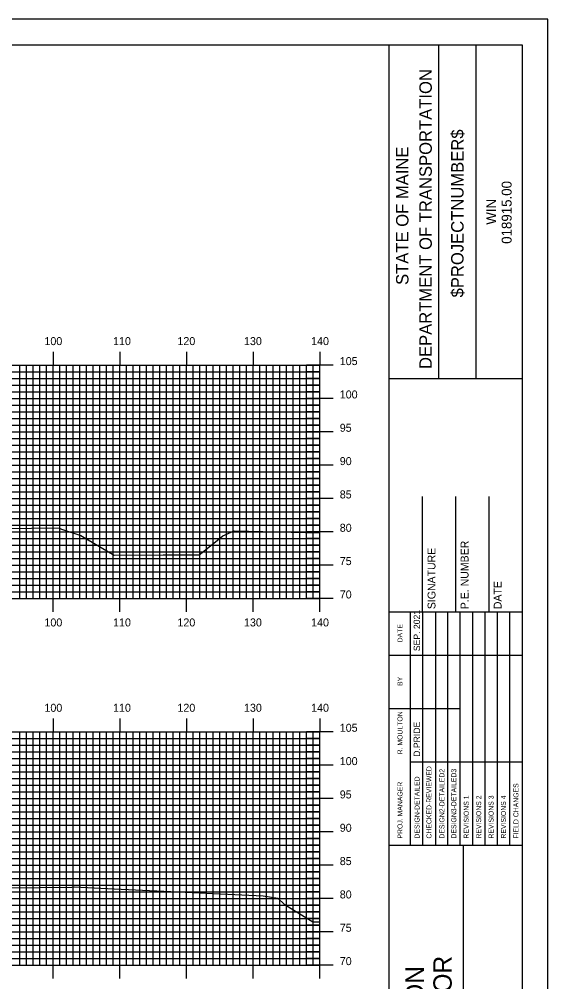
# Model space of a CAD drawing. Extents: x 1756282 to 1756625, y 442591 to 442811.
# Drawn here: x 1756542.5 to 1756621.8, y 442666.2 to 442810.5 of the extents above; entities that cross this region are included whole.
import ezdxf

# ---------------------------------------------------------------- set-up
doc = ezdxf.new("R2010")
doc.units = 0
for name, color, linetype in [('BORDER', 7, 'Continuous'), ('H_V ANNOTATION', 7, 'Continuous'), ('MAJOR', 7, 'Continuous'), ('MINOR', 7, 'Continuous'), ('PLOT BOUNDARY', 7, 'Continuous'), ('S_Roadway_Centerline', 7, 'Continuous')]:
    doc.layers.add(name, color=color, linetype=linetype)

msp = doc.modelspace()

# ---------------------------------------------------------------- linework, layer by layer
at = {"layer": 'BORDER'}
for p, q in [((1756597.97, 442596.67), (1756597.97, 442806.67)), ((1756605.43, 442756.66), (1756605.43, 442806.66)), ((1756611.02, 442756.66), (1756611.02, 442806.66)), ((1756597.97, 442756.65), (1756617.97, 442756.65)), ((1756602.97, 442721.67), (1756602.97, 442738.97)), ((1756607.97, 442721.67), (1756607.97, 442738.97)), ((1756612.97, 442721.67), (1756612.97, 442738.97)), ((1756597.97, 442721.67), (1756617.97, 442721.67)), ((1756597.97, 442686.67), (1756617.97, 442686.67)), ((1756609.15, 442616.67), (1756609.15, 442686.67))]:
    msp.add_line(p, q, dxfattribs=at)
msp.add_lwpolyline([(1756297.97, 442596.67), (1756617.97, 442596.67), (1756617.97, 442806.67), (1756297.97, 442806.67)], close=True, dxfattribs=at)
for points in [[(1756601.2, 442715.17), (1756601.2, 442721.67)], [(1756603.06, 442686.68), (1756603.06, 442721.67)], [(1756604.93, 442721.67), (1756604.93, 442686.68)], [(1756606.79, 442686.68), (1756606.79, 442721.67)], [(1756608.65, 442686.68), (1756608.65, 442721.67)], [(1756610.52, 442686.68), (1756610.52, 442721.67)], [(1756612.38, 442686.68), (1756612.38, 442721.67)], [(1756614.24, 442686.68), (1756614.24, 442721.67)], [(1756616.11, 442686.68), (1756616.11, 442721.67)], [(1756601.2, 442686.68), (1756601.2, 442720.26)], [(1756597.97, 442715.17), (1756617.97, 442715.17)], [(1756597.97, 442707.17), (1756601.2, 442707.17)], [(1756601.2, 442707.17), (1756608.65, 442707.17)], [(1756601.2, 442699.17), (1756617.97, 442699.17)]]:
    msp.add_lwpolyline(points, dxfattribs=at)
at = {"layer": 'MAJOR'}
for p, q in [((1756547.57, 442760.67), (1756547.57, 442758.67)), ((1756557.57, 442760.67), (1756557.57, 442758.67)), ((1756567.57, 442760.67), (1756567.57, 442758.67)), ((1756577.57, 442760.67), (1756577.57, 442758.67)), ((1756587.57, 442760.67), (1756587.57, 442758.67)), ((1756307.57, 442758.67), (1756587.57, 442758.67)), ((1756307.57, 442758.67), (1756587.57, 442758.67)), ((1756547.57, 442723.67), (1756547.57, 442758.67)), ((1756557.57, 442723.67), (1756557.57, 442758.67)), ((1756567.57, 442723.67), (1756567.57, 442758.67)), ((1756577.57, 442723.67), (1756577.57, 442758.67)), ((1756589.57, 442758.67), (1756585.57, 442758.67)), ((1756587.57, 442723.67), (1756587.57, 442758.67)), ((1756587.57, 442723.67), (1756587.57, 442758.67)), ((1756307.57, 442753.67), (1756587.57, 442753.67)), ((1756589.57, 442753.67), (1756585.57, 442753.67)), ((1756307.57, 442748.67), (1756587.57, 442748.67)), ((1756589.57, 442748.67), (1756585.57, 442748.67)), ((1756307.57, 442743.67), (1756587.57, 442743.67)), ((1756589.57, 442743.67), (1756585.57, 442743.67)), ((1756307.57, 442738.67), (1756587.57, 442738.67)), ((1756589.57, 442738.67), (1756585.57, 442738.67)), ((1756307.57, 442733.67), (1756587.57, 442733.67)), ((1756589.57, 442733.67), (1756585.57, 442733.67)), ((1756307.57, 442728.67), (1756587.57, 442728.67)), ((1756589.57, 442728.67), (1756585.57, 442728.67)), ((1756307.57, 442723.67), (1756587.57, 442723.67)), ((1756307.57, 442723.67), (1756587.57, 442723.67)), ((1756547.57, 442721.66), (1756547.57, 442723.67)), ((1756557.57, 442721.66), (1756557.57, 442723.67)), ((1756567.57, 442721.66), (1756567.57, 442723.67)), ((1756577.57, 442721.66), (1756577.57, 442723.67)), ((1756589.57, 442723.67), (1756585.57, 442723.67)), ((1756587.57, 442721.66), (1756587.57, 442723.67)), ((1756547.57, 442705.67), (1756547.57, 442703.67)), ((1756557.57, 442705.67), (1756557.57, 442703.67)), ((1756567.57, 442705.67), (1756567.57, 442703.67)), ((1756577.57, 442705.67), (1756577.57, 442703.67)), ((1756587.57, 442705.67), (1756587.57, 442703.67)), ((1756307.57, 442703.67), (1756587.57, 442703.67)), ((1756307.57, 442703.67), (1756587.57, 442703.67)), ((1756547.57, 442668.67), (1756547.57, 442703.67)), ((1756557.57, 442668.67), (1756557.57, 442703.67)), ((1756567.57, 442668.67), (1756567.57, 442703.67)), ((1756577.57, 442668.67), (1756577.57, 442703.67)), ((1756589.57, 442703.67), (1756585.57, 442703.67)), ((1756587.57, 442668.67), (1756587.57, 442703.67)), ((1756587.57, 442668.67), (1756587.57, 442703.67)), ((1756307.57, 442698.67), (1756587.57, 442698.67)), ((1756589.57, 442698.67), (1756585.57, 442698.67)), ((1756307.57, 442693.67), (1756587.57, 442693.67)), ((1756589.57, 442693.67), (1756585.57, 442693.67)), ((1756307.57, 442688.67), (1756587.57, 442688.67)), ((1756589.57, 442688.67), (1756585.57, 442688.67)), ((1756307.57, 442683.67), (1756587.57, 442683.67)), ((1756589.57, 442683.67), (1756585.57, 442683.67)), ((1756307.57, 442678.67), (1756587.57, 442678.67)), ((1756589.57, 442678.67), (1756585.57, 442678.67)), ((1756307.57, 442673.67), (1756587.57, 442673.67)), ((1756589.57, 442673.67), (1756585.57, 442673.67)), ((1756307.57, 442668.67), (1756587.57, 442668.67)), ((1756307.57, 442668.67), (1756587.57, 442668.67)), ((1756547.57, 442666.66), (1756547.57, 442668.67)), ((1756557.57, 442666.66), (1756557.57, 442668.67)), ((1756567.57, 442666.66), (1756567.57, 442668.67)), ((1756577.57, 442666.66), (1756577.57, 442668.67)), ((1756589.57, 442668.67), (1756585.57, 442668.67)), ((1756587.57, 442666.66), (1756587.57, 442668.67))]:
    msp.add_line(p, q, dxfattribs=at)
at = {"layer": 'MINOR'}
for p, q in [((1756542.57, 442723.67), (1756542.57, 442758.67)), ((1756543.57, 442723.67), (1756543.57, 442758.67)), ((1756544.57, 442723.67), (1756544.57, 442758.67)), ((1756545.57, 442723.67), (1756545.57, 442758.67)), ((1756546.57, 442723.67), (1756546.57, 442758.67)), ((1756548.57, 442723.67), (1756548.57, 442758.67)), ((1756549.57, 442723.67), (1756549.57, 442758.67)), ((1756550.57, 442723.67), (1756550.57, 442758.67)), ((1756551.57, 442723.67), (1756551.57, 442758.67)), ((1756552.57, 442723.67), (1756552.57, 442758.67)), ((1756553.57, 442723.67), (1756553.57, 442758.67)), ((1756554.57, 442723.67), (1756554.57, 442758.67)), ((1756555.57, 442723.67), (1756555.57, 442758.67)), ((1756556.57, 442723.67), (1756556.57, 442758.67)), ((1756558.57, 442723.67), (1756558.57, 442758.67)), ((1756559.57, 442723.67), (1756559.57, 442758.67)), ((1756560.57, 442723.67), (1756560.57, 442758.67)), ((1756561.57, 442723.67), (1756561.57, 442758.67)), ((1756562.57, 442723.67), (1756562.57, 442758.67)), ((1756563.57, 442723.67), (1756563.57, 442758.67)), ((1756564.57, 442723.67), (1756564.57, 442758.67)), ((1756565.57, 442723.67), (1756565.57, 442758.67)), ((1756566.57, 442723.67), (1756566.57, 442758.67)), ((1756568.57, 442723.67), (1756568.57, 442758.67)), ((1756569.57, 442723.67), (1756569.57, 442758.67)), ((1756570.57, 442723.67), (1756570.57, 442758.67)), ((1756571.57, 442723.67), (1756571.57, 442758.67)), ((1756572.57, 442723.67), (1756572.57, 442758.67)), ((1756573.57, 442723.67), (1756573.57, 442758.67)), ((1756574.57, 442723.67), (1756574.57, 442758.67)), ((1756575.57, 442723.67), (1756575.57, 442758.67)), ((1756576.57, 442723.67), (1756576.57, 442758.67)), ((1756578.57, 442723.67), (1756578.57, 442758.67)), ((1756579.57, 442723.67), (1756579.57, 442758.67)), ((1756580.57, 442723.67), (1756580.57, 442758.67)), ((1756581.57, 442723.67), (1756581.57, 442758.67)), ((1756582.57, 442723.67), (1756582.57, 442758.67)), ((1756583.57, 442723.67), (1756583.57, 442758.67)), ((1756584.57, 442723.67), (1756584.57, 442758.67)), ((1756585.57, 442723.67), (1756585.57, 442758.67)), ((1756586.57, 442723.67), (1756586.57, 442758.67)), ((1756307.57, 442757.67), (1756587.57, 442757.67)), ((1756587.57, 442757.67), (1756585.57, 442757.67)), ((1756307.57, 442756.67), (1756587.57, 442756.67)), ((1756307.57, 442755.67), (1756587.57, 442755.67)), ((1756587.57, 442756.67), (1756585.57, 442756.67)), ((1756587.57, 442755.67), (1756585.57, 442755.67)), ((1756307.57, 442754.67), (1756587.57, 442754.67)), ((1756587.57, 442754.67), (1756585.57, 442754.67)), ((1756307.57, 442752.67), (1756587.57, 442752.67)), ((1756307.57, 442751.67), (1756587.57, 442751.67)), ((1756587.57, 442752.67), (1756585.57, 442752.67)), ((1756587.57, 442751.67), (1756585.57, 442751.67)), ((1756307.57, 442750.67), (1756587.57, 442750.67)), ((1756587.57, 442750.67), (1756585.57, 442750.67)), ((1756307.57, 442749.67), (1756587.57, 442749.67)), ((1756587.57, 442749.67), (1756585.57, 442749.67)), ((1756307.57, 442747.67), (1756587.57, 442747.67)), ((1756587.57, 442747.67), (1756585.57, 442747.67)), ((1756307.57, 442746.67), (1756587.57, 442746.67)), ((1756307.57, 442745.67), (1756587.57, 442745.67)), ((1756587.57, 442746.67), (1756585.57, 442746.67)), ((1756587.57, 442745.67), (1756585.57, 442745.67)), ((1756307.57, 442744.67), (1756587.57, 442744.67)), ((1756587.57, 442744.67), (1756585.57, 442744.67)), ((1756307.57, 442742.67), (1756587.57, 442742.67)), ((1756587.57, 442742.67), (1756585.57, 442742.67)), ((1756307.57, 442741.67), (1756587.57, 442741.67)), ((1756587.57, 442741.67), (1756585.57, 442741.67)), ((1756307.57, 442740.67), (1756587.57, 442740.67)), ((1756587.57, 442740.67), (1756585.57, 442740.67)), ((1756307.57, 442739.67), (1756587.57, 442739.67)), ((1756587.57, 442739.67), (1756585.57, 442739.67)), ((1756307.57, 442737.67), (1756587.57, 442737.67)), ((1756587.57, 442737.67), (1756585.57, 442737.67)), ((1756307.57, 442736.67), (1756587.57, 442736.67)), ((1756307.57, 442735.67), (1756587.57, 442735.67)), ((1756587.57, 442736.67), (1756585.57, 442736.67)), ((1756587.57, 442735.67), (1756585.57, 442735.67)), ((1756307.57, 442734.67), (1756587.57, 442734.67)), ((1756587.57, 442734.67), (1756585.57, 442734.67)), ((1756307.57, 442732.67), (1756587.57, 442732.67)), ((1756587.57, 442732.67), (1756585.57, 442732.67)), ((1756307.57, 442731.67), (1756587.57, 442731.67)), ((1756587.57, 442731.67), (1756585.57, 442731.67)), ((1756307.57, 442730.67), (1756587.57, 442730.67)), ((1756307.57, 442729.67), (1756587.57, 442729.67)), ((1756587.57, 442730.67), (1756585.57, 442730.67)), ((1756587.57, 442729.67), (1756585.57, 442729.67)), ((1756307.57, 442727.67), (1756587.57, 442727.67)), ((1756587.57, 442727.67), (1756585.57, 442727.67)), ((1756307.57, 442726.67), (1756587.57, 442726.67)), ((1756307.57, 442725.67), (1756587.57, 442725.67)), ((1756587.57, 442726.67), (1756585.57, 442726.67)), ((1756587.57, 442725.67), (1756585.57, 442725.67)), ((1756307.57, 442724.67), (1756587.57, 442724.67)), ((1756587.57, 442724.67), (1756585.57, 442724.67)), ((1756542.57, 442668.67), (1756542.57, 442703.67)), ((1756543.57, 442668.67), (1756543.57, 442703.67)), ((1756544.57, 442668.67), (1756544.57, 442703.67)), ((1756545.57, 442668.67), (1756545.57, 442703.67)), ((1756546.57, 442668.67), (1756546.57, 442703.67)), ((1756548.57, 442668.67), (1756548.57, 442703.67)), ((1756549.57, 442668.67), (1756549.57, 442703.67)), ((1756550.57, 442668.67), (1756550.57, 442703.67)), ((1756551.57, 442668.67), (1756551.57, 442703.67)), ((1756552.57, 442668.67), (1756552.57, 442703.67)), ((1756553.57, 442668.67), (1756553.57, 442703.67)), ((1756554.57, 442668.67), (1756554.57, 442703.67)), ((1756555.57, 442668.67), (1756555.57, 442703.67)), ((1756556.57, 442668.67), (1756556.57, 442703.67)), ((1756558.57, 442668.67), (1756558.57, 442703.67)), ((1756559.57, 442668.67), (1756559.57, 442703.67)), ((1756560.57, 442668.67), (1756560.57, 442703.67)), ((1756561.57, 442668.67), (1756561.57, 442703.67)), ((1756562.57, 442668.67), (1756562.57, 442703.67)), ((1756563.57, 442668.67), (1756563.57, 442703.67)), ((1756564.57, 442668.67), (1756564.57, 442703.67)), ((1756565.57, 442668.67), (1756565.57, 442703.67)), ((1756566.57, 442668.67), (1756566.57, 442703.67)), ((1756568.57, 442668.67), (1756568.57, 442703.67)), ((1756569.57, 442668.67), (1756569.57, 442703.67)), ((1756570.57, 442668.67), (1756570.57, 442703.67)), ((1756571.57, 442668.67), (1756571.57, 442703.67)), ((1756572.57, 442668.67), (1756572.57, 442703.67)), ((1756573.57, 442668.67), (1756573.57, 442703.67)), ((1756574.57, 442668.67), (1756574.57, 442703.67)), ((1756575.57, 442668.67), (1756575.57, 442703.67)), ((1756576.57, 442668.67), (1756576.57, 442703.67)), ((1756578.57, 442668.67), (1756578.57, 442703.67)), ((1756579.57, 442668.67), (1756579.57, 442703.67)), ((1756580.57, 442668.67), (1756580.57, 442703.67)), ((1756581.57, 442668.67), (1756581.57, 442703.67)), ((1756582.57, 442668.67), (1756582.57, 442703.67)), ((1756583.57, 442668.67), (1756583.57, 442703.67)), ((1756584.57, 442668.67), (1756584.57, 442703.67)), ((1756585.57, 442668.67), (1756585.57, 442703.67)), ((1756586.57, 442668.67), (1756586.57, 442703.67)), ((1756307.57, 442702.67), (1756587.57, 442702.67)), ((1756587.57, 442702.67), (1756585.57, 442702.67)), ((1756307.57, 442701.67), (1756587.57, 442701.67)), ((1756587.57, 442701.67), (1756585.57, 442701.67)), ((1756307.57, 442700.67), (1756587.57, 442700.67)), ((1756307.57, 442699.67), (1756587.57, 442699.67)), ((1756587.57, 442700.67), (1756585.57, 442700.67)), ((1756587.57, 442699.67), (1756585.57, 442699.67)), ((1756307.57, 442697.67), (1756587.57, 442697.67)), ((1756307.57, 442696.67), (1756587.57, 442696.67)), ((1756587.57, 442697.67), (1756585.57, 442697.67)), ((1756587.57, 442696.67), (1756585.57, 442696.67)), ((1756307.57, 442695.67), (1756587.57, 442695.67)), ((1756587.57, 442695.67), (1756585.57, 442695.67)), ((1756307.57, 442694.67), (1756587.57, 442694.67)), ((1756587.57, 442694.67), (1756585.57, 442694.67)), ((1756307.57, 442692.67), (1756587.57, 442692.67)), ((1756587.57, 442692.67), (1756585.57, 442692.67)), ((1756307.57, 442691.67), (1756587.57, 442691.67)), ((1756307.57, 442690.67), (1756587.57, 442690.67)), ((1756587.57, 442691.67), (1756585.57, 442691.67)), ((1756587.57, 442690.67), (1756585.57, 442690.67)), ((1756307.57, 442689.67), (1756587.57, 442689.67)), ((1756587.57, 442689.67), (1756585.57, 442689.67)), ((1756307.57, 442687.67), (1756587.57, 442687.67)), ((1756307.57, 442686.67), (1756587.57, 442686.67)), ((1756587.57, 442687.67), (1756585.57, 442687.67)), ((1756587.57, 442686.67), (1756585.57, 442686.67)), ((1756307.57, 442685.67), (1756587.57, 442685.67)), ((1756587.57, 442685.67), (1756585.57, 442685.67)), ((1756307.57, 442684.67), (1756587.57, 442684.67)), ((1756587.57, 442684.67), (1756585.57, 442684.67)), ((1756307.57, 442682.67), (1756587.57, 442682.67)), ((1756587.57, 442682.67), (1756585.57, 442682.67)), ((1756307.57, 442681.67), (1756587.57, 442681.67)), ((1756307.57, 442680.67), (1756587.57, 442680.67)), ((1756587.57, 442681.67), (1756585.57, 442681.67)), ((1756587.57, 442680.67), (1756585.57, 442680.67)), ((1756307.57, 442679.67), (1756587.57, 442679.67)), ((1756587.57, 442679.67), (1756585.57, 442679.67)), ((1756307.57, 442677.67), (1756587.57, 442677.67)), ((1756587.57, 442677.67), (1756585.57, 442677.67)), ((1756307.57, 442676.67), (1756587.57, 442676.67)), ((1756587.57, 442676.67), (1756585.57, 442676.67)), ((1756307.57, 442675.67), (1756587.57, 442675.67)), ((1756587.57, 442675.67), (1756585.57, 442675.67)), ((1756307.57, 442674.67), (1756587.57, 442674.67)), ((1756587.57, 442674.67), (1756585.57, 442674.67)), ((1756307.57, 442672.67), (1756587.57, 442672.67)), ((1756587.57, 442672.67), (1756585.57, 442672.67)), ((1756307.57, 442671.67), (1756587.57, 442671.67)), ((1756307.57, 442670.67), (1756587.57, 442670.67)), ((1756587.57, 442671.67), (1756585.57, 442671.67)), ((1756587.57, 442670.67), (1756585.57, 442670.67)), ((1756307.57, 442669.67), (1756587.57, 442669.67)), ((1756587.57, 442669.67), (1756585.57, 442669.67))]:
    msp.add_line(p, q, dxfattribs=at)
at = {"layer": 'PLOT BOUNDARY'}
msp.add_lwpolyline([(1756281.78, 442590.55), (1756621.78, 442590.55), (1756621.78, 442810.55), (1756281.78, 442810.55)], close=True, dxfattribs=at)
at = {"layer": 'S_Roadway_Centerline'}
for points in [[(1756527.75, 442734.03), (1756548.47, 442734.25), (1756548.8, 442734.04), (1756551.69, 442733.1), (1756556.73, 442730.15), (1756564.07, 442730.22), (1756569.45, 442730.21), (1756572.16, 442732.38), (1756573.01, 442733.08), (1756574.74, 442733.79), (1756587.57, 442733.49)], [(1756398.08, 442679.98), (1756402.56, 442679.91), (1756404.87, 442679.86), (1756422.76, 442679.94), (1756444.5, 442679.93), (1756448.72, 442680.09), (1756452.91, 442680.01), (1756471.12, 442680.02), (1756493.51, 442679.73), (1756497.21, 442679.76), (1756504.87, 442679.61), (1756518.11, 442679.86), (1756535.57, 442680.21), (1756550.37, 442680.37), (1756550.69, 442680.4), (1756556.7, 442680.11), (1756579.05, 442679.06), (1756581.27, 442678.69), (1756582.24, 442677.83), (1756586.52, 442675.15), (1756587.57, 442675.15)]]:
    msp.add_lwpolyline(points, dxfattribs=at)

# ---------------------------------------------------------------- texts
at = {"layer": 'BORDER'}
for s, height, p in [('DEPARTMENT OF TRANSPORTATION', 1.8635, (1756604.38, 442758.08)), ('$PROJECTNUMBER$', 1.8635, (1756609.15, 442768.82)), ('STATE OF MAINE', 1.8635, (1756600.88, 442770.69)), ('018915.00', 1.491, (1756616.36, 442776.86)), ('WIN', 1.491, (1756614.04, 442779.73)), ('SIGNATURE', 1.181, (1756604.93, 442722.06)), ('P.E. NUMBER', 1.1811, (1756609.89, 442722.06)), ('DATE', 1.181, (1756614.85, 442722.06)), ('SEP. 2021', 0.969, (1756602.62, 442715.76)), ('DATE', 0.743, (1756599.98, 442717.08)), ('BY', 0.743, (1756599.98, 442710.54)), ('R. MOULTON', 0.745, (1756599.98, 442700.28)), ('D.PRIDE', 0.969, (1756602.62, 442699.92)), ('CHECKED-REVIEWED', 0.7455, (1756604.33, 442687.65)), ('DESIGN-DETAILED', 0.7455, (1756602.54, 442687.65)), ('DESIGN2-DETAILED2', 0.7455, (1756606.27, 442687.65)), ('DESIGN3-DETAILED3', 0.7455, (1756608.06, 442687.65)), ('PROJ. MANAGER', 0.7455, (1756599.98, 442687.65)), ('FIELD CHANGES', 0.7455, (1756617.38, 442687.65)), ('REVISIONS 1', 0.7455, (1756609.92, 442687.65)), ('REVISIONS 2', 0.7455, (1756611.79, 442687.65)), ('REVISIONS 3', 0.7455, (1756613.65, 442687.65)), ('REVISIONS 4', 0.7455, (1756615.51, 442687.65)), ('1-395/ROUTE 9 CONNECTOR', 2.7557, (1756607.37, 442618.87)), ('BREWER TO EDDINGTON', 2.7557, (1756603.19, 442623.07))]:
    msp.add_text(s, height=height, rotation=90, dxfattribs=at).set_placement(p)
at = {"layer": 'H_V ANNOTATION'}
for s, p in [('100', (1756546.25, 442761.67)), ('110', (1756556.55, 442761.67)), ('120', (1756566.21, 442761.67)), ('130', (1756576.2, 442761.67)), ('140', (1756586.27, 442761.67)), ('105', (1756590.57, 442758.67)), ('100', (1756590.57, 442753.67)), ('95', (1756590.57, 442748.67)), ('90', (1756590.57, 442743.67)), ('85', (1756590.57, 442738.67)), ('80', (1756590.57, 442733.67)), ('75', (1756590.57, 442728.67)), ('70', (1756590.57, 442723.67)), ('100', (1756546.25, 442719.47)), ('110', (1756556.55, 442719.47)), ('120', (1756566.21, 442719.47)), ('130', (1756576.2, 442719.47)), ('140', (1756586.27, 442719.47)), ('100', (1756546.25, 442706.67)), ('110', (1756556.55, 442706.67)), ('120', (1756566.21, 442706.67)), ('130', (1756576.2, 442706.67)), ('140', (1756586.27, 442706.67)), ('105', (1756590.57, 442703.67)), ('100', (1756590.57, 442698.67)), ('95', (1756590.57, 442693.67)), ('90', (1756590.57, 442688.67)), ('85', (1756590.57, 442683.67)), ('80', (1756590.57, 442678.67)), ('75', (1756590.57, 442673.67)), ('70', (1756590.57, 442668.67))]:
    msp.add_text(s, height=1.2, dxfattribs=at).set_placement(p)

doc.saveas('drawing.dxf')
